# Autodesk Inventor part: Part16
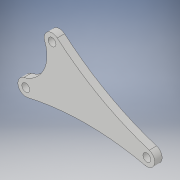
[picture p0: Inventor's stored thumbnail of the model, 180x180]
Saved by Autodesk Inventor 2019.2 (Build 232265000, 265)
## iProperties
Created: 2019-04
Part Number: Part16
Material: Generic
Document SubType Name: Modeling
Designer: richard.girt
Mass: 1.65683 g
Surface Area: 16.3203 cm^2
Volume: 1.65683 cm^3
Density: 1 g/cm^3
Appearance: Default
Author: richard.girt
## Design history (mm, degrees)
sketch "Sketch1"
  geometry: L1 (11.457, 22.622)-(47.457, 2.622); L2 (46, -3)-(0, -3); L3 (-2.683, 1.342)-(7.317, 21.342); L4 (77.011, 98.221)-(29.457, 12.622); L5 (23, -100.399)-(23, -3); L6 (-3.944, 14.472)-(2.317, 11.342); C1 r 1.5 at (0, 0); C2 r 1.5 at (10, 20); C3 r 1.5 at (46, 0); A1 r 3 centre (10, 20) between (11.952, 22.278) and (7.211, 18.894); A2 r 3 centre (0, 0) between (-0.789, 2.894) and (0.67, -2.924); A3 r 3 centre (46, 0) between (45.33, -2.924) and (46.903, 2.861); A4 r 100 centre (77.011, 98.221) between (11.952, 22.278) and (46.903, 2.861); A5 r 12 centre (-3.944, 14.472) between (-0.789, 2.894) and (7.211, 18.894); A6 r 100 centre (23, -100.399) between (45.33, -2.924) and (0.67, -2.924); 1 further point
  constraints: 18 point on circle, 12 end point, 9 centre point, 9 tangent, 7 coincident, 4 equal radius, 3 midpoint, 3 perpendicular
  dimensions: "d0" = 3 diameter of C1; "d1" = 10 horizontal distance of C2.centre point (0, 0); "d2" = 20 vertical distance of C2.centre point (0, 0); "d3" = 46 distance of C3.centre point (0, 0); "d4" = 0 vertical distance of point (0, 0) C3.centre; "d5" = 6 diameter of A3; "d6" = 12 radius of A5; "d7" = 100 radius of A6; "d8" = 100 radius of A4
extrude "Extrusion1" new body sketch "Sketch1" stored distance "d9" = 2.8; taper "d10" = 0 deg
body "Solid1"
